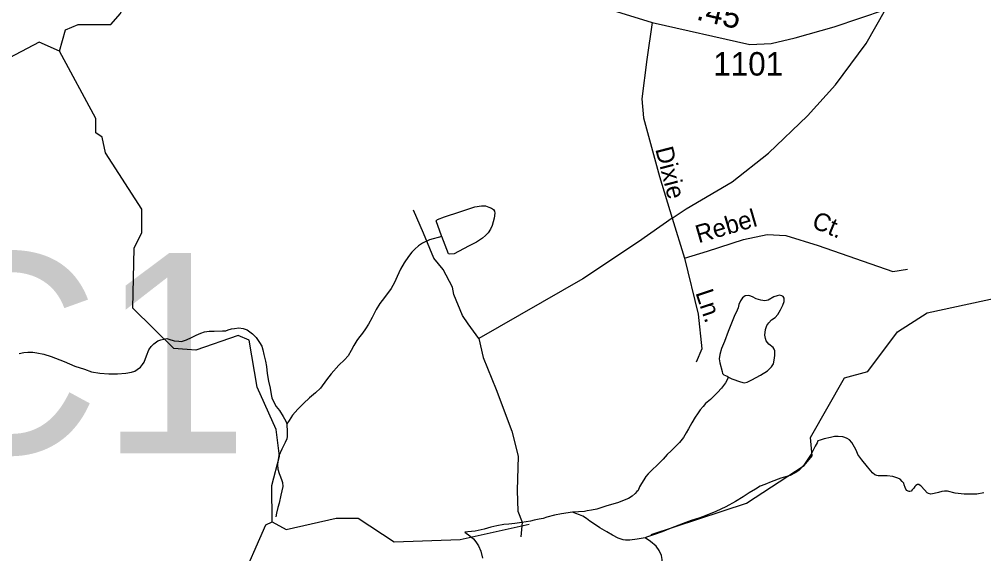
# Model space of a CAD drawing. Extents: x 2126262 to 2293712, y 749403 to 919119.
# Drawn here: x 2178899 to 2184028, y 798555 to 801398 of the extents above; entities that cross this region are included whole.
import ezdxf

# ---------------------------------------------------------------- set-up
doc = ezdxf.new("R2010")
doc.units = 0
for name, color, linetype in [('Exist Hydrographic Creek Single Shore', 7, 'Continuous'), ('Exist Hydrographic Misc Water Feature', 7, 'Continuous'), ('Exist Road Non-System Type 51', 7, 'Continuous'), ('Exist Road Non-System Type 51 Label', 7, 'Continuous'), ('Exist Road Secondary Mileage Hundredths English Label', 7, 'Continuous'), ('Exist Road Secondary Structure Culvert Number Label', 7, 'Continuous'), ('Exist Road Secondary Type 51 Attributed', 7, 'Continuous'), ('Exist Road Secondary Type 51 Number Label', 7, 'Continuous')]:
    doc.layers.add(name, color=color, linetype=linetype)

msp = doc.modelspace()

# ---------------------------------------------------------------- linework, layer by layer
at = {"layer": 'Exist Hydrographic Creek Single Shore'}
for points in [[(2179112.5, 801227.6), (2179145.5, 801341.7), (2179212.6, 801369.9), (2179386.7, 801369.5), (2179436.5, 801427.6), (2179494.5, 801570.7), (2179576.5, 801637.9), (2179967.6, 801846.4), (2181010.5, 802953.4), (2181251.6, 803096), (2181500.5, 803297.6), (2181924.6, 803508.7), (2182164.5, 803667.8)], [(2179112.5, 801227.6), (2179004.7, 801275.7), (2178813.5, 801174.7), (2178721.5, 801215.9), (2178478.5, 801457.1), (2178286.6, 801464.3), (2178177.5, 801588), (2178168.7, 801804.7), (2178084.6, 801911.5)], [(2180243.6, 798724.2), (2180242.5, 798917.8), (2180282.5, 799074.4), (2180265.5, 799215.8), (2180164.6, 799441), (2180121.6, 799691.1), (2180062.5, 799715.3), (2179838.6, 799638), (2179721.5, 799646.9), (2179503.5, 799861.4), (2179510.5, 800179.5), (2179551.5, 800263.9), (2179550.5, 800388.5), (2179357.5, 800687.8), (2179340.5, 800770.2), (2179306.5, 800793.8), (2179306.5, 800869.3), (2179112.5, 801227.6)], [(2180011.5, 796344), (2179947.5, 796414.2), (2179930.2, 796438.3), (2179922.4, 796456.7), (2179924.6, 796482.4), (2179954.5, 796537.2), (2179953.7, 796592), (2179971.5, 796656.5), (2179945.6, 796765.3), (2180020.5, 796875.3), (2180043.4, 797216), (2179959.6, 797375.2), (2179975.6, 797440.4), (2180058.6, 797550.2), (2180098.6, 797723.3), (2180105.6, 798084), (2180071.5, 798206.1), (2180069.5, 798389.9), (2180209.5, 798708.5), (2180243.6, 798724.2)]]:
    msp.add_lwpolyline(points, dxfattribs=at)
at = {"layer": 'Exist Hydrographic Misc Water Feature'}
for points in [[(2183073.5, 799023.5), (2183115.5, 799075.1), (2183106.5, 799173.7), (2183287.6, 799491.4), (2183412.4, 799525), (2183569.5, 799735), (2183727.6, 799836.7), (2184326.6, 799965.4), (2184632.5, 800425), (2184656.5, 800614.8), (2184639.5, 800657.8), (2184638.4, 800766), (2184704.5, 800833.6), (2184904.6, 800885.2), (2184945.6, 800943.4), (2185073, 800976)], [(2181147, 800241.7), (2181144.8, 800245.7), (2181116.2, 800325.5), (2181122.4, 800333.5), (2181160.3, 800347.6), (2181242.2, 800374.2), (2181321.7, 800400.7), (2181357.8, 800405), (2181377.7, 800404.8), (2181395.9, 800398.8), (2181409.7, 800393.1), (2181421.6, 800385.2), (2181426.3, 800377.2), (2181427.9, 800367.2), (2181424.2, 800339.4), (2181414, 800301.2), (2181404.8, 800281.1), (2181392.5, 800261), (2181378.7, 800246.9), (2181362.7, 800233), (2181330.9, 800212.7), (2181288.9, 800190.6), (2181211.2, 800150), (2181189.2, 800148.1), (2181181.5, 800149.7), (2181147, 800241.7)], [(2181147, 800241.7), (2181081, 800225.3), (2181043, 800207.1), (2181023, 800193.1), (2181003.3, 800175), (2180987.5, 800158.8), (2180969.4, 800136.7), (2180945.4, 800102.6), (2180925.8, 800068.7), (2180907.9, 800030.4), (2180894, 799998.4), (2180876.3, 799966.2), (2180840.7, 799918), (2180816.7, 799886), (2180796.8, 799853.6), (2180775.5, 799811.4), (2180755.4, 799775.6), (2180740, 799751.5), (2180724, 799727.5), (2180703.9, 799701.4), (2180693.8, 799689.5), (2180678.5, 799663), (2180664.5, 799635.2), (2180648.7, 799607.1), (2180628.4, 799587), (2180598.5, 799558.7), (2180556.9, 799512.6), (2180533.3, 799480.5), (2180501.3, 799436.2), (2180474, 799410), (2180442, 799384), (2180410.3, 799353.9), (2180380.1, 799323.5), (2180352.2, 799291.6), (2180334.4, 799263.5), (2180321.7, 799245.1)], [(2182670.5, 799494.5), (2182688.4, 799484.5), (2182734.7, 799468.6), (2182754.4, 799464.9), (2182770.6, 799466.9), (2182794.2, 799479.1), (2182840.3, 799505.4), (2182878.5, 799527.7), (2182900, 799550), (2182910.3, 799565.8), (2182913.7, 799584), (2182918, 799609.7), (2182917.2, 799633.7), (2182913.3, 799643.7), (2182907.6, 799651.9), (2182885.4, 799669.8), (2182871.3, 799687.3), (2182867, 799699.3), (2182863.3, 799717.4), (2182867, 799747.6), (2182874.8, 799769.6), (2182884.8, 799783.5), (2182898.6, 799799.7), (2182918.5, 799811.6), (2182932.6, 799827.8), (2182948, 799851.8), (2182960.5, 799877.9), (2182966, 799896.1), (2182966, 799914), (2182961.7, 799924), (2182954.1, 799926), (2182941.8, 799929.8), (2182930.1, 799927.6), (2182912.1, 799921.8), (2182882, 799903.6), (2182863.7, 799899.5), (2182842, 799903.2), (2182818.2, 799911.2), (2182798.1, 799921.1), (2182783.7, 799926.9), (2182776.1, 799928.9), (2182759.9, 799926.9), (2182746, 799916.8), (2182734.3, 799900.7), (2182726.3, 799880.4), (2182722, 799862.5), (2182716.7, 799850.7), (2182700.9, 799816.6), (2182686.7, 799780.5), (2182668.7, 799736.2), (2182649.4, 799684.4), (2182633.4, 799646.2), (2182623.8, 799614), (2182621.7, 799592), (2182624.2, 799570.1), (2182636.5, 799524.1), (2182638.1, 799514.1), (2182646.6, 799506.3), (2182662.8, 799498.6), (2182670.5, 799494.5)], [(2179684.2, 799699.7), (2179694.2, 799695.8), (2179722.1, 799687.9), (2179748.1, 799686), (2179762.3, 799683.9), (2179788.3, 799692.1), (2179814.2, 799704.4), (2179839.8, 799718.4), (2179864, 799728.6), (2179884.3, 799734.8), (2179908.3, 799738.9), (2179936, 799738.8), (2179980.1, 799741), (2179997.9, 799741.2), (2180010, 799745.4), (2180027.6, 799751.7), (2180043.8, 799753.7), (2180065.8, 799755.7), (2180089.8, 799753.7), (2180111.7, 799745.9), (2180140, 799724.1), (2180158, 799704.4), (2180176.1, 799678.5), (2180188.2, 799658.4), (2180194.5, 799640.4), (2180200.3, 799614.4), (2180208.9, 799578.7), (2180213, 799550.4), (2180217.3, 799514.5), (2180225.1, 799472.7), (2180233.3, 799435), (2180237.8, 799402.7), (2180241.7, 799385), (2180251.8, 799364.8), (2180265.7, 799338.8), (2180282.1, 799317.2), (2180302.4, 799285.4), (2180316.8, 799259.3), (2180321.7, 799245.1)], [(2178899, 799619.2), (2178923, 799625.4), (2178945, 799627.3), (2178971, 799627.4), (2178992.9, 799623.7), (2179029, 799615.8), (2179069, 799604.1), (2179137.3, 799576.8), (2179195.3, 799552.9), (2179245.4, 799537.2), (2179283.5, 799523.4), (2179327.6, 799515.5), (2179375.4, 799511.9), (2179421.5, 799512.3), (2179465, 799516.2), (2179495.5, 799520.6), (2179513.2, 799526.8), (2179525.5, 799534.7), (2179543.1, 799547), (2179554.8, 799561.1), (2179563.2, 799574.8), (2179576.5, 799606.9), (2179588.6, 799639.1), (2179600.7, 799657.2), (2179614.4, 799671.3), (2179636.2, 799687.5), (2179652.2, 799693.2), (2179684.2, 799699.7)], [(2182670.5, 799494.5), (2182654.6, 799464.5), (2182632.8, 799436.1), (2182613.1, 799412), (2182595.3, 799394), (2182575.2, 799375.9), (2182548.9, 799353.9), (2182535.2, 799337.7), (2182519.6, 799319.8), (2182505.5, 799299.6), (2182493.6, 799281.5), (2182476, 799251.3), (2182457.7, 799219.2), (2182446, 799197.5), (2182432.3, 799173.2), (2182410.5, 799147.2), (2182390.6, 799127.1), (2182366.5, 799102.8), (2182344.5, 799082.6), (2182323, 799058.6), (2182291.4, 799026.5), (2182265.4, 799000.4), (2182243.2, 798980.2), (2182231.5, 798966.2), (2182219.6, 798948.1), (2182207.7, 798928), (2182198.1, 798910), (2182189.9, 798891.7), (2182183.8, 798885.7), (2182174.1, 798875.9), (2182158.1, 798861.6), (2182138.2, 798849.6), (2182116.3, 798839.6), (2182086.6, 798827.5), (2182056.2, 798819), (2182024.4, 798809.3), (2181996.7, 798800.8), (2181970.3, 798792.7), (2181943, 798786.6), (2181918.8, 798782.6), (2181904.5, 798780.3), (2181840.9, 798776.1)], [(2180321.7, 799245.1), (2180322.7, 799239.3), (2180324.5, 799209.4), (2180322.9, 799179.2), (2180321.1, 799165.3), (2180313.5, 799147.4), (2180295, 799111.2), (2180279.2, 799075.1), (2180275.7, 799057), (2180273.9, 799045.1), (2180271.6, 799027.1), (2180274.1, 799005.3), (2180280.3, 798981.2), (2180288.2, 798963.3), (2180296.2, 798945.1), (2180298.1, 798933.5), (2180300.8, 798913.2), (2180296.2, 798889.1), (2180290.5, 798867.3), (2180281.1, 798823.2), (2180274.9, 798801.1), (2180267.3, 798771), (2180263.6, 798751.3)], [(2184029.4, 798878.2), (2183991.5, 798872.2), (2183923.4, 798871.5), (2183875.4, 798877.5), (2183835.4, 798887.2), (2183819.2, 798887.2), (2183805.5, 798886.9), (2183787.7, 798881.1), (2183765.3, 798874.7), (2183747.5, 798872.5), (2183733.5, 798874.7), (2183727.4, 798878.4), (2183713.4, 798894.3), (2183695, 798914.5), (2183689.2, 798918.2), (2183683.1, 798922.4), (2183675.1, 798922.4), (2183667.3, 798918.3), (2183661.6, 798912.3), (2183655.6, 798904.3), (2183647.4, 798894.1), (2183641.5, 798888.1), (2183635.5, 798886.2), (2183631.2, 798886), (2183625.7, 798888.1), (2183619.5, 798891.9), (2183613.8, 798898), (2183609.5, 798908), (2183605.4, 798922), (2183603.3, 798930), (2183593.5, 798939.6), (2183583, 798951.8), (2183571.3, 798957.6), (2183545.5, 798965.6), (2183515.2, 798969.3), (2183497.1, 798969.2), (2183467, 798969.3), (2183459.2, 798970.9), (2183448.9, 798974.9), (2183436.8, 798984.8), (2183410.8, 799016.7), (2183380.4, 799054.6), (2183358.3, 799082.3), (2183350.7, 799102.5), (2183340.4, 799122.3), (2183326.1, 799146.4), (2183314, 799160.4), (2183302.1, 799168.2), (2183290, 799174.1), (2183277.9, 799176), (2183254.1, 799177.9), (2183234, 799177.7), (2183213.7, 799173.5), (2183180.1, 799165.6), (2183158.4, 799159.2), (2183146.1, 799155.3)], [(2183146.1, 799155.3), (2183142.4, 799145.3), (2183132.1, 799127.4), (2183110.6, 799085.2), (2183070.8, 799026.8), (2183044.8, 798998.6), (2183025.1, 798984.6), (2182999.4, 798970.6), (2182949.4, 798956.2), (2182897.5, 798938.1), (2182863.7, 798923.8), (2182839.9, 798913.6), (2182813.7, 798899.3), (2182779.8, 798879.2), (2182748.1, 798857.3), (2182708.3, 798832.8), (2182656, 798804.6), (2182602.7, 798780.2), (2182554.7, 798759.9), (2182518.8, 798745.9), (2182472.7, 798731.7), (2182429, 798715.2), (2182360.9, 798689), (2182317.2, 798670.9), (2182271.1, 798654.7), (2182235, 798642.3), (2182227.4, 798640.2)], [(2182260.3, 798656.8), (2182766.5, 798823.1), (2183073.5, 799023.5)], [(2181840.9, 798776.1), (2181782.5, 798767.5), (2181744.7, 798759.4), (2181705.2, 798749.2), (2181685.1, 798743.3), (2181663.1, 798738.9), (2181636.9, 798732.7), (2181617.2, 798728.8), (2181571.1, 798720.4), (2181535.2, 798716.5), (2181503, 798712), (2181475.5, 798710.1), (2181439.2, 798703.8), (2181407.2, 798695.7), (2181371.5, 798685.2), (2181323.6, 798675), (2181283.8, 798670.9), (2181269.4, 798669)], [(2182227.4, 798640.2), (2182185.4, 798632), (2182145.6, 798627.8), (2182123.5, 798627.5), (2182109.7, 798629.6), (2182083.3, 798637.3), (2182053.3, 798653.2), (2182023.2, 798671.1), (2181987.3, 798692.7), (2181963.1, 798708.6), (2181932.8, 798728.6), (2181914.7, 798742.3), (2181896.7, 798754.3), (2181879, 798762.2), (2181858.7, 798768.2), (2181840.9, 798776.1)], [(2180243.6, 798724.2), (2180318.6, 798683.3), (2180584.6, 798743.4), (2180701.4, 798744.3), (2180893.6, 798619), (2181243.6, 798631.5), (2181610.2, 798713.1)], [(2181269.4, 798669), (2181295.7, 798650.8), (2181313.9, 798635.1), (2181327.9, 798619.2), (2181342, 798597.2), (2181353.9, 798569.4), (2181362.5, 798531.2)], [(2182304.5, 798428.6), (2182314.6, 798438.8), (2182318.3, 798452.9), (2182320.3, 798474.9), (2182320.5, 798496.8), (2182317.9, 798524.7), (2182314, 798544.8), (2182301.7, 798572.6), (2182285.3, 798594.6), (2182255.7, 798620.6), (2182227.4, 798640.2)]]:
    msp.add_lwpolyline(points, dxfattribs=at)
at = {"layer": 'Exist Road Non-System Type 51'}
msp.add_line((2182370.6, 800340.5), (2182435.9, 800126.7), dxfattribs=at)
for points in [[(2182370.6, 800340.5), (2182445.3, 800389.9), (2182690.7, 800532.5), (2182882.7, 800686.1), (2183090, 800883.3), (2183239.8, 801048.4), (2183403.7, 801268.6), (2183506.1, 801450.3)], [(2182264.4, 801381.2), (2182236.2, 801184.1), (2182210.6, 800974.1), (2182218.3, 800874.3), (2182304.1, 800560.7), (2182370.6, 800340.5)], [(2181342.3, 799700.7), (2181285.8, 799778.2), (2181256.5, 799822.9), (2181210.4, 799934.6), (2181202.1, 799972.3), (2181152.5, 800066.6), (2181103.7, 800126.6), (2181047.9, 800260.7), (2180996.3, 800382.2)], [(2182370.6, 800340.5), (2182192.7, 800213.8), (2181895.7, 800016.6), (2181342.3, 799700.7)], [(2182435.9, 800126.7), (2182558.8, 800165.1), (2182750.8, 800226.6), (2182876.4, 800253), (2182975.5, 800247.4), (2183147.1, 800194.4), (2183544.1, 800056.8), (2183622.2, 800069.4)], [(2182435.9, 800126.7), (2182510.2, 799829.7), (2182529, 799645.5), (2182498.3, 799574.3)], [(2181342.3, 799700.7), (2181365.3, 799599.4), (2181435.1, 799429.1), (2181518.1, 799207.7), (2181551.6, 799073.7), (2181546, 798892.1), (2181550.9, 798781.1), (2181573.2, 798722.4), (2181566.2, 798645.6)]]:
    msp.add_lwpolyline(points, dxfattribs=at)
at = {"layer": 'Exist Road Secondary Type 51 Attributed'}
msp.add_lwpolyline([(2181301.8, 801970.1), (2181574.7, 801686.2), (2181686.3, 801603.8), (2181924.2, 801478.8), (2182074.9, 801439.7), (2182264.4, 801381.2), (2182784.1, 801263.5), (2182896.8, 801268.6), (2183024.8, 801299.3), (2183232.1, 801358.2), (2183506.1, 801450.3)], dxfattribs=at)

# ---------------------------------------------------------------- texts
at = {"layer": 'Exist Road Non-System Type 51 Label'}
for s, rotation, p in [('Dixie', 284.5069, (2182280.7, 800707.5)), ('Rebel', 16.3036, (2182511.3, 800206.2)), ('Ct.', 337.4126, (2183107.6, 800292.4)), ('Ln.', 288.4176, (2182494.3, 799943.6))]:
    msp.add_text(s, height=95, rotation=rotation, dxfattribs=at).set_placement(p)
at = {"layer": 'Exist Road Secondary Mileage Hundredths English Label'}
msp.add_text('.45', height=125, rotation=346.8098, dxfattribs=at).set_placement((2182494.6, 801397.1))
at = {"layer": 'Exist Road Secondary Structure Culvert Number Label'}
msp.add_text('C1', height=1066.27, dxfattribs=at).set_placement((2178298.4, 799088.7))
at = {"layer": 'Exist Road Secondary Type 51 Number Label'}
msp.add_text('1101', height=125, dxfattribs=at).set_placement((2182589.7, 801098.3))

doc.saveas('drawing.dxf')
